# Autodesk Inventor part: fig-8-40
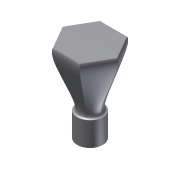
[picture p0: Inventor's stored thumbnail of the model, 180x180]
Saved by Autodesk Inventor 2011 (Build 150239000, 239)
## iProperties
Created: 2004-05
Part Number: fig-8-40
Document SubType Name: Modeling
Designer: CADCIM Technologies
Manufacturer: Standard
Standards Organization: Custom
Density: 1 g/cm^3
Author: CADCIM Technologies
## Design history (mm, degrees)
sketch "Sketch1"
  geometry: C1 r 16.344 at (0, 0)
  constraints: 1 centre point
extrude "Extrusion1" new body sketch "Sketch1" distance "d0" = 30.75; taper "d1" = 0 deg
workplane "Work Plane1"
sketch "Sketch2"
  geometry: L1 (34.788, 0)-(17.394, -30.128); L2 (17.394, -30.128)-(-17.394, -30.128); L3 (-17.394, -30.128)-(-34.788, 0); L4 (-34.788, 0)-(-17.394, 30.128); L5 (-17.394, 30.128)-(17.394, 30.128); L6 (17.394, 30.128)-(34.788, 0); 2 further points
  constraints: 12 end point, 1 coincident, 12 other
loft "Loft2" sketch "Sketch2" dims "d9" = 5, "d10" = 90 deg, "d11" = 40, "d12" = 120 deg
  node "Edges2"
body "Solid1"
other parameters: "d2" = 75
